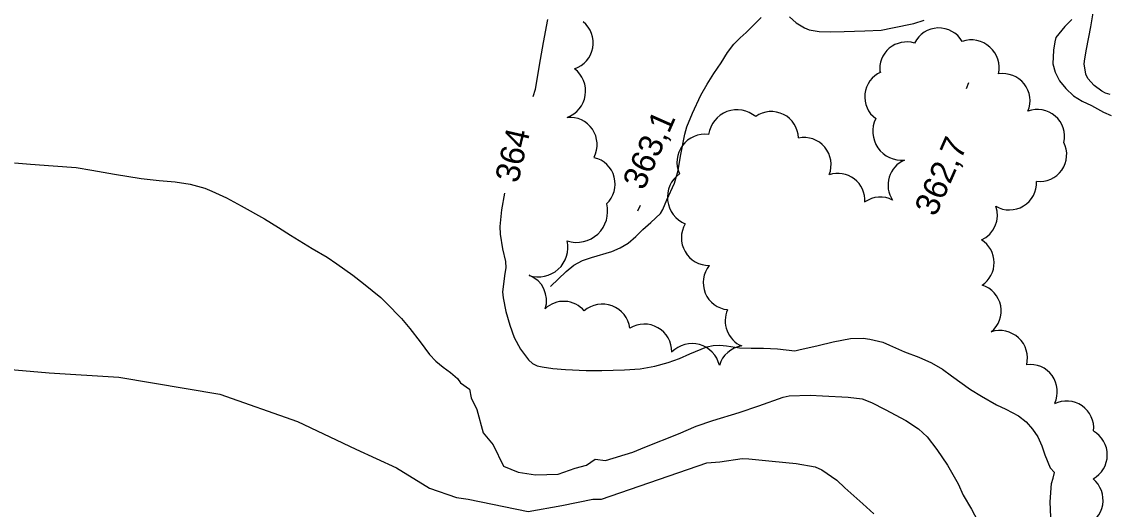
# Model space of a CAD drawing. Extents: x 287698 to 290158, y 5234163 to 5237182.
# Drawn here: x 288226.3 to 288362.3, y 5235620.4 to 5235681.4 of the extents above; entities that cross this region are included whole.
import ezdxf

# ---------------------------------------------------------------- set-up
doc = ezdxf.new("R2010")
doc.units = 0
for name, color, linetype in [('Niveau 2', 7, 'Continuous'), ('Niveau 3', 7, 'Continuous'), ('Niveau 4', 7, 'Continuous'), ('Niveau 44', 7, 'Continuous')]:
    doc.layers.add(name, color=color, linetype=linetype)

msp = doc.modelspace()

# ---------------------------------------------------------------- linework, layer by layer
at = {"layer": 'Niveau 2'}
for points in [[(288292.12, 5235681.72), (288291.61, 5235678.81), (288291.11, 5235675.97), (288290.57, 5235672.95), (288290.31, 5235672.02)], [(288225.42, 5235663.76), (288227.4, 5235663.6), (288230.24, 5235663.39), (288233.14, 5235663.16), (288235.08, 5235662.84), (288237.94, 5235662.33), (288241.28, 5235661.8), (288243.51, 5235661.56), (288245.52, 5235661.39), (288247.41, 5235661.08), (288249.22, 5235660.59), (288250.13, 5235660.23), (288251.97, 5235659.37), (288253.78, 5235658.37), (288256.69, 5235656.73), (288258.45, 5235655.67), (288259.98, 5235654.69), (288262.66, 5235653.04), (288264.56, 5235651.94), (288265.78, 5235651.12), (288267.76, 5235649.7), (288269.12, 5235648.66), (288271.29, 5235646.88), (288271.92, 5235646.23), (288273.84, 5235644.28), (288274.89, 5235643.03), (288276.21, 5235641.33), (288277.36, 5235639.78), (288278.17, 5235638.93), (288279.07, 5235638.17), (288280.01, 5235637.51), (288280.87, 5235636.74), (288281.24, 5235636.23), (288282.36, 5235635.41), (288282.36, 5235635.41)], [(288286.73, 5235659.98), (288286.37, 5235657.88), (288286.17, 5235655.81), (288286.21, 5235654.83), (288286.49, 5235653), (288286.87, 5235651.4), (288286.91, 5235650.63), (288286.8, 5235649.89), (288286.5, 5235647.62), (288286.57, 5235646.84), (288286.92, 5235645.15), (288287.41, 5235643.44), (288287.98, 5235641.88), (288288.77, 5235640.42), (288289.75, 5235639.11), (288290.26, 5235638.63), (288290.84, 5235638.33), (288291.46, 5235638.2), (288292.82, 5235638.02), (288294.39, 5235637.9), (288296.96, 5235637.76), (288298.94, 5235637.78), (288301.78, 5235637.85), (288303.74, 5235637.99), (288305.57, 5235638.32), (288307.25, 5235638.78), (288308.67, 5235639.28), (288309.95, 5235639.84), (288312.08, 5235640.72), (288312.87, 5235640.89), (288313.71, 5235640.93), (288314.53, 5235640.84), (288316.15, 5235640.58), (288317.61, 5235640.54), (288319.17, 5235640.56), (288320.91, 5235640.46), (288323.08, 5235640.24)], [(288323.08, 5235640.24), (288323.58, 5235640.36), (288326, 5235640.88), (288327.88, 5235641.34), (288330.05, 5235641.76), (288331.66, 5235641.8), (288332.46, 5235641.67), (288334.11, 5235641.29), (288334.96, 5235640.94), (288336.82, 5235640.08), (288338.61, 5235639.41), (288340.21, 5235638.7), (288341.56, 5235637.93), (288342.71, 5235637.08), (288345.1, 5235635.39), (288346.44, 5235634.56), (288348.34, 5235633.45), (288349.52, 5235632.93), (288351.11, 5235632.1), (288352.07, 5235631.34), (288352.84, 5235630.43), (288353.49, 5235629.47), (288354.02, 5235628.32), (288354.39, 5235627.19), (288355.05, 5235625.58), (288355.6, 5235625), (288355.6, 5235625)], [(288223.5, 5235638.03), (288229.77, 5235637.45), (288238.48, 5235636.93), (288251.12, 5235634.8), (288260.83, 5235631.38), (288268.13, 5235627.9), (288273.23, 5235625.59), (288277.37, 5235623.02), (288280.76, 5235621.87), (288282.22, 5235621.66)], [(288282.36, 5235635.41), (288282.57, 5235634.33), (288283.27, 5235632.88), (288284.1, 5235629.95), (288285.34, 5235628.45), (288286.61, 5235625.77), (288288.48, 5235625.03), (288290.62, 5235624.71), (288292.05, 5235624.74), (288293.48, 5235624.77), (288295.61, 5235625.53), (288297.03, 5235625.9), (288298.09, 5235626.64), (288299.4, 5235626.49), (288302.81, 5235627.52), (288304.3, 5235628.16), (288308.55, 5235629.85), (288310.74, 5235630.79), (288312.82, 5235631.51), (288316.13, 5235632.51), (288318.58, 5235633.32), (288321.65, 5235634.43), (288322.37, 5235634.59), (288325.02, 5235634.66), (288326.54, 5235634.59), (288329.76, 5235634.41), (288331.5, 5235634.2), (288332.69, 5235633.76), (288334.39, 5235632.89), (288336.97, 5235631.48)], [(288336.97, 5235631.48), (288338.56, 5235630.47), (288339.66, 5235629.47), (288340.87, 5235627.89), (288342.2, 5235625.89), (288343.52, 5235623.55), (288344.15, 5235622.14), (288345.21, 5235620.41), (288345.97, 5235618.96), (288346.56, 5235616.97), (288346.77, 5235615.34), (288346.62, 5235613.87), (288346.28, 5235612.22), (288345.6, 5235609.83), (288344.91, 5235608), (288343.87, 5235604.88), (288343.18, 5235602.85), (288341.25, 5235598.89)], [(288282.22, 5235621.66), (288289.72, 5235620.11), (288293.92, 5235620.84), (288297.82, 5235621.64), (288298.9, 5235621.66), (288312.07, 5235626.22), (288313.71, 5235626.34), (288316.48, 5235626.74), (288317.34, 5235626.72), (288320.26, 5235626.4), (288323.24, 5235626.12), (288325.65, 5235625.7), (288326.49, 5235625.32), (288328.37, 5235624.01), (288329.35, 5235623.06), (288331.62, 5235621.05), (288333, 5235619.8)], [(288345.95, 5235592.81), (288346.99, 5235595.49), (288348.31, 5235598.5), (288349.69, 5235601.67), (288351.2, 5235605.2), (288352.33, 5235607.75), (288353.39, 5235610.19), (288354.55, 5235613.09), (288354.81, 5235614.19), (288355.14, 5235616.76), (288355.18, 5235618.43), (288355.05, 5235621.3), (288355.24, 5235623.62), (288355.42, 5235624.27), (288355.6, 5235625)]]:
    msp.add_lwpolyline(points, dxfattribs=at)
at = {"layer": 'Niveau 3'}
for p, q in [((288344.57, 5235673.08), (288344.89, 5235673.81)), ((288303.45, 5235657.74), (288303.77, 5235658.47))]:
    msp.add_line(p, q, dxfattribs=at)
at = {"layer": 'Niveau 4'}
for points in [[(288362.57, 5235672.31), (288361.98, 5235672.49), (288361.54, 5235672.75), (288360.56, 5235673.44), (288359.77, 5235674.31), (288359.53, 5235674.88), (288359.33, 5235676.15), (288359.39, 5235676.8), (288359.61, 5235678.01), (288360.13, 5235680.77), (288360.49, 5235682.8)], [(288292.49, 5235648.28), (288294.45, 5235650.16), (288295.42, 5235650.96), (288296.51, 5235651.55), (288297.63, 5235651.89), (288300.17, 5235652.65), (288301.24, 5235653.1), (288302.21, 5235653.71), (288303.17, 5235654.53), (288304.07, 5235655.43), (288305.05, 5235656.28), (288306.27, 5235657.42), (288306.57, 5235657.92), (288307.09, 5235659.11), (288308.05, 5235661.2), (288308.47, 5235662.8), (288308.79, 5235664.6), (288309.31, 5235667.35), (288309.58, 5235668.25), (288310.29, 5235669.97), (288311.32, 5235672.23), (288312.11, 5235673.63), (288312.97, 5235674.96), (288313.87, 5235676.29), (288314.67, 5235677.57), (288315.47, 5235678.63), (288316.26, 5235679.41), (288317.01, 5235680.09), (288318.87, 5235681.94)], [(288322.43, 5235682.06), (288323.25, 5235681.28), (288324.29, 5235680.65), (288324.87, 5235680.43), (288326.12, 5235680.19), (288327.51, 5235680.16), (288329.26, 5235680.2), (288331.86, 5235680.27), (288333.9, 5235680.39), (288335.3, 5235680.65), (288337.99, 5235681.22), (288339.29, 5235681.61)], [(288357.75, 5235681.69), (288356.91, 5235680.82), (288355.77, 5235679.44), (288355.64, 5235678.93), (288355.46, 5235677.86), (288355.38, 5235676.17), (288355.67, 5235675.12), (288356.23, 5235674.05), (288357, 5235673.05), (288357.97, 5235672.17), (288359.05, 5235671.5), (288360.22, 5235670.94), (288361.74, 5235670.12), (288362.7, 5235669.69)]]:
    msp.add_lwpolyline(points, dxfattribs=at)
at = {"layer": 'Niveau 44'}
for centre, radius, start, end in [((288311.84, 5235663.83), 3.51, 82.5033, 204.3168), ((288315.02, 5235648.76), 3.4, 140.7338, 264.1825)]:
    msp.add_arc(centre, radius, start, end, dxfattribs=at)
for centre, major_axis, ratio, start_param, end_param in [((288294.43, 5235678.79), (-1.17, 3.22), 0.999995, 3.12056, 5.243041), ((288341.12, 5235677.26), (-1.65, -2.96), 0.999845, 2.606425, 4.763126), ((288337.1, 5235675.52), (-3.22, 1.03), 0.999215, 4.730536, 6.714716), ((288345.16, 5235675.64), (2.33, 2.64), 0.994882, 5.218168, 7.333219), ((288293.36, 5235672.75), (3.4, -0.99), 0.999775, 5.351885, 7.476657), ((288335.23, 5235672.03), (1.83, -2.85), 0.999882, 2.992934, 5.078676), ((288349.13, 5235671.53), (2.67, 2.11), 0.999433, 5.222042, 7.346026), ((288315.87, 5235666.8), (-0.55, -3.56), 0.999985, 2.590548, 4.721965), ((288320.16, 5235666.79), (-0.03, 3.39), 0.999857, 4.729113, 6.892055), ((288353.47, 5235667.06), (2.9, 1.76), 0.999777, 5.51897, 7.671562), ((288294.94, 5235666.06), (2.9, 1.78), 0.999324, 5.250479, 7.402275), ((288336.47, 5235667.7), (-2.98, -2.06), 0.999021, 5.219712, 7.34598), ((288324.23, 5235663.53), (-2.19, 2.61), 0.999984, 3.638905, 5.785873), ((288353.74, 5235664.81), (1.95, 2.77), 0.999858, 3.636265, 5.788513), ((288297.2, 5235661.1), (3.22, 1.09), 0.999685, 5.143613, 7.294573), ((288338.15, 5235660.98), (-0.31, -3.38), 0.999858, 3.637132, 5.392451), ((288310.74, 5235659.46), (-3.59, -0.18), 0.999206, 5.284791, 7.414989), ((288328.47, 5235659.06), (-2.47, 2.32), 0.999984, 3.834865, 5.787543), ((288349.96, 5235661.25), (2.89, 1.76), 0.999859, 3.632477, 5.792301), ((288333.79, 5235656.09), (-3.38, -0.12), 0.999984, 4.20214, 5.284843), ((288295.78, 5235657.68), (-0.91, 3.77), 0.999987, 2.592587, 4.722279), ((288345.06, 5235657.19), (2.27, 2.51), 0.999859, 4.302291, 5.789976), ((288312.37, 5235654.38), (-3.04, -1.7), 0.993892, 5.237816, 7.352489), ((288291.01, 5235653.16), (2.27, -2.89), 0.999354, 5.29452, 7.417112), ((288344.65, 5235651.25), (-0.33, 3.37), 0.999858, 3.63428, 5.619526), ((288288.6, 5235646.5), (-0.42, 3.39), 0.999984, 4.282469, 5.784542), ((288345.54, 5235645.21), (-2.83, 1.85), 0.999778, 2.835157, 4.992212), ((288294.16, 5235643.02), (0.08, 3.4), 0.998291, 5.442833, 7.066418), ((288298.99, 5235642.55), (1.23, 3.29), 0.998633, 5.220616, 7.341167), ((288317.77, 5235643.96), (-2.8, -1.92), 0.998739, 5.254576, 6.852067), ((288304.25, 5235640.12), (-3.45, -0.05), 0.999995, 3.114344, 5.244802), ((288348.75, 5235639.3), (2.48, 2.42), 0.998509, 5.270637, 7.393868), ((288310.21, 5235637.6), (0.96, 3.4), 0.999995, 5.21821, 7.350717), ((288316.92, 5235637.47), (-3.32, -0.73), 0.999937, 4.638623, 5.787822), ((288352.56, 5235635.12), (-2, 2.74), 0.999984, 3.637532, 5.787246), ((288357.12, 5235630.56), (2.05, 2.7), 0.998175, 5.250696, 7.40413), ((288358.77, 5235627.2), (3.39, -0.56), 0.999828, 5.377239, 7.499209), ((288358.26, 5235621.53), (3.37, -0.59), 0.999978, 5.220954, 7.342977)]:
    msp.add_ellipse(centre, major_axis=major_axis, ratio=ratio, start_param=start_param, end_param=end_param, dxfattribs=at)

# ---------------------------------------------------------------- texts
at = {"layer": 'Niveau 2'}
msp.add_text('364', height=3, rotation=76.8946, dxfattribs=at).set_placement((288288.45, 5235661.12))
at = {"layer": 'Niveau 3'}
for s, p in [('363,1', (288304.16, 5235660.2)), ('362,7', (288340.71, 5235656.92))]:
    msp.add_text(s, height=3, rotation=66.1217, dxfattribs=at).set_placement(p)

doc.saveas('drawing.dxf')
